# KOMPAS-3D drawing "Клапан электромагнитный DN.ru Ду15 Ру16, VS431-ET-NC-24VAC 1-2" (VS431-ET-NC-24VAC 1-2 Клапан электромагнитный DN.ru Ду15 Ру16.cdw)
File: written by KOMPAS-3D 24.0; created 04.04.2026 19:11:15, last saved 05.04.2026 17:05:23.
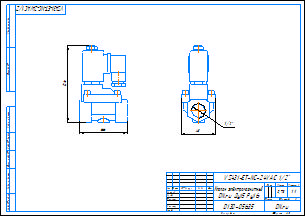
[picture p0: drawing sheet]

Document properties: c3d_UniqueCompID: ef56311e-7521-43dc-8291-0e6108b3d81d; Обозначение: VS400-ET-NC-220VAC 1-2; Наименование: Клапан электромагнитный DN.ru Ду15 Ру16; Автор: artio; Класс точности: c; Знак неуказанной шероховатости: Шероховатость не задана; Рассекать на разрезах: Да; c3d_UniqueCompID: ef56311e-7521-43dc-8291-0e6108b3d81d; Обозначение: VS400-ET-NC-220VAC 3-8; Наименование: Клапан электромагнитный DN.ru Ду10 Ру16; Автор: artio; Класс точности: c; Знак неуказанной шероховатости: Шероховатость не задана; Рассекать на разрезах: Да; Автор: artio; Форматы листов документа: A3; Полное имя файла: VS431-ET-NC-24VAC 1-2 Клапан электромагнитный DN.ru Ду15 Ру16.m3d; Масса: 0.732; Наименование: Клапан электромагнитный DN.ru Ду15 Ру16; Количество листов документа: 1; Примечание: D130-05635

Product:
- Body: Тело 1  | qty 1
    Масса: 1.030062
- Part/product: Клапан электромагнитный DN.ru Ду15 Ру16  | designation VS431-ET-NC-24VAC 1-2
    Масса: 0.732
    Раздел спецификации: Прочие изделия
    Примечание: D130-05635
    additional columns: ef56311e-7521-43dc-8291-0e6108b3d81d; VS400-ET-NC-220VAC 1-2; artio; c; Шероховатость не задана; Да

Views: Вид 1, Спереди, Проекционный вид 2
Referenced files in C:\Users\artio\OneDrive\Рабочий стол\Клапан электромагнитный DN.ru\VS400-ET-NC\VS400-ET-NC-24VDC\: VS400-ET-NC-24VDC 3-8 Клапан электромагнитный DN.ru Ду10 Ру16.m3d
Referenced files in C:\Users\artio\OneDrive\Рабочий стол\Клапан электромагнитный DN.ru\VS431\VS431-ET-NC\VS431-ET-NC-24VAC\Ду15\: VS431-ET-NC-24VAC 1-2 Клапан электромагнитный DN.ru Ду15 Ру16.m3d
Referenced files in C:\Users\artio\OneDrive\Рабочий стол\Клапан электромагнитный DN.ru\VS400-ET-NC\: VS400-ET-NC-24VDC 3-8 Клапан электромагнитный DN.ru Ду10 Ру16.cdw
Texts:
  VS431-ET-NC-24VAC 1-2
  Клапан электромагнитный
  DN.ru Ду15 Ру16
  VS431-ET-NC-24VAC 1/2"
  VS431-ET-NC-24VAC 1/2"-
  Клапан электромагнитный DN.ru Ду15 Ру16
  VS431-ET-NC-24VAC 1-2 Клапан электромагнитный DN.ru Ду15 Ру16
Dimensions and other numbers on the sheet: 0; 3; 2; 4; 48; 1/2"; 66; 106; 1:1; 1; 0,73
